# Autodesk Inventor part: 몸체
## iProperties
Created: 2012-05
Part Number: 몸체
Document SubType Name: 모델링
Designer: SeoGD™
변환 표준: STEP AP214IS
파일 이름: C:\Users\SeoGD\Desktop\?쒗뿕\紐몄껜.stp
전처리기: Build: 253, Release: 2010 SP1 - Date: Wed 07/29/2009
전송 단위: 밀리미터
불확실성: 0.01
Author: SeoGD™
